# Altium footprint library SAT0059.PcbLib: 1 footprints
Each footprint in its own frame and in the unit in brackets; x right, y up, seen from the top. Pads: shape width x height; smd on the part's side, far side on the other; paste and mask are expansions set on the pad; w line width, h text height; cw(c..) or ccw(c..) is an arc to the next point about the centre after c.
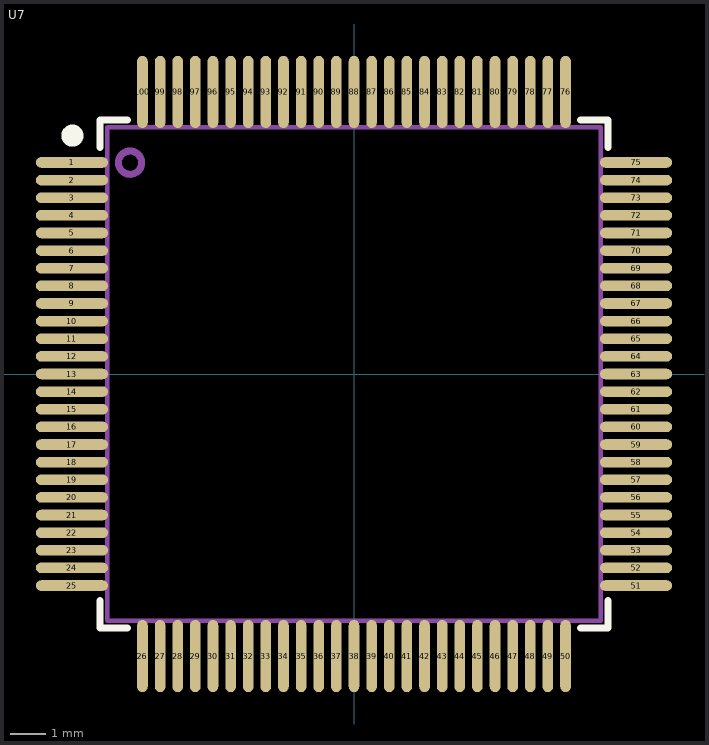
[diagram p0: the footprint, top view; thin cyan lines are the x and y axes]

## U7 [mm] "100-pin QFP"
height 1.6
pads (100):
  oval 2.05x0.3 smd mask+0.025: 1(-8,6) 2(-8,5.5) 3(-8,5) 4(-8,4.5) 5(-8,4) 6(-8,3.5) 7(-8,3) 8(-8,2.5) 9(-8,2) 10(-8,1.5) 11(-8,1) 12(-8,0.5) 13(-8,0) 14(-8,-0.5) 15(-8,-1) 16(-8,-1.5) 17(-8,-2) 18(-8,-2.5) 19(-8,-3) 20(-8,-3.5) 21(-8,-4) 22(-8,-4.5) 23(-8,-5) 24(-8,-5.5) 25(-8,-6) 51(8,-6) 52(8,-5.5) 53(8,-5) 54(8,-4.5) 55(8,-4) 56(8,-3.5) 57(8,-3) 58(8,-2.5) 59(8,-2) 60(8,-1.5) 61(8,-1) 62(8,-0.5) 63(8,0) 64(8,0.5) 65(8,1) 66(8,1.5) 67(8,2) 68(8,2.5) 69(8,3) 70(8,3.5) 71(8,4) 72(8,4.5) 73(8,5) 74(8,5.5) 75(8,6)
  oval 0.3x2.05 smd mask+0.025: 26(-6,-8) 27(-5.5,-8) 28(-5,-8) 29(-4.5,-8) 30(-4,-8) 31(-3.5,-8) 32(-3,-8) 33(-2.5,-8) 34(-2,-8) 35(-1.5,-8) 36(-1,-8) 37(-0.5,-8) 38(0,-8) 39(0.5,-8) 40(1,-8) 41(1.5,-8) 42(2,-8) 43(2.5,-8) 44(3,-8) 45(3.5,-8) 46(4,-8) 47(4.5,-8) 48(5,-8) 49(5.5,-8) 50(6,-8) 76(6,8) 77(5.5,8) 78(5,8) 79(4.5,8) 80(4,8) 81(3.5,8) 82(3,8) 83(2.5,8) 84(2,8) 85(1.5,8) 86(1,8) 87(0.5,8) 88(0,8) 89(-0.5,8) 90(-1,8) 91(-1.5,8) 92(-2,8) 93(-2.5,8) 94(-3,8) 95(-3.5,8) 96(-4,8) 97(-4.5,8) 98(-5,8) 99(-5.5,8) 100(-6,8)
Top Overlay:
  lines w0.2: -7.2,-6.426 -7.2,-7.2 -6.426,-7.2 ; -7.2,6.426 -7.2,7.2 -6.426,7.2 ; 6.426,-7.2 7.2,-7.2 7.2,-6.426 ; 6.426,7.2 7.2,7.2 7.2,6.426
  lines w0.4: -7.875,6.78 ccw(c-7.988,6.761) -7.874,6.756
M5 Assembly Top:
  lines w0.127: -7,-7 -7,7 7,7 7,-7 -7,-7
  lines w0.2: -6.641,5.836 cw(c-6.352,5.994) -6.629,5.817
  text ".Designator" at -2.6,-0.3 h1.02
3D body: height 1.61, standoff -0.01, extent -8,-8 8,8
